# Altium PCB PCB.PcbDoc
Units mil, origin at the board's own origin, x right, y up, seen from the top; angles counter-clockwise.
Board outline 2700 x 2300 mil, 2 copper layers (Top Layer, Bottom Layer), stack 62 mil thick; 67 components, 35 nets, 208 pads, 314 vias.
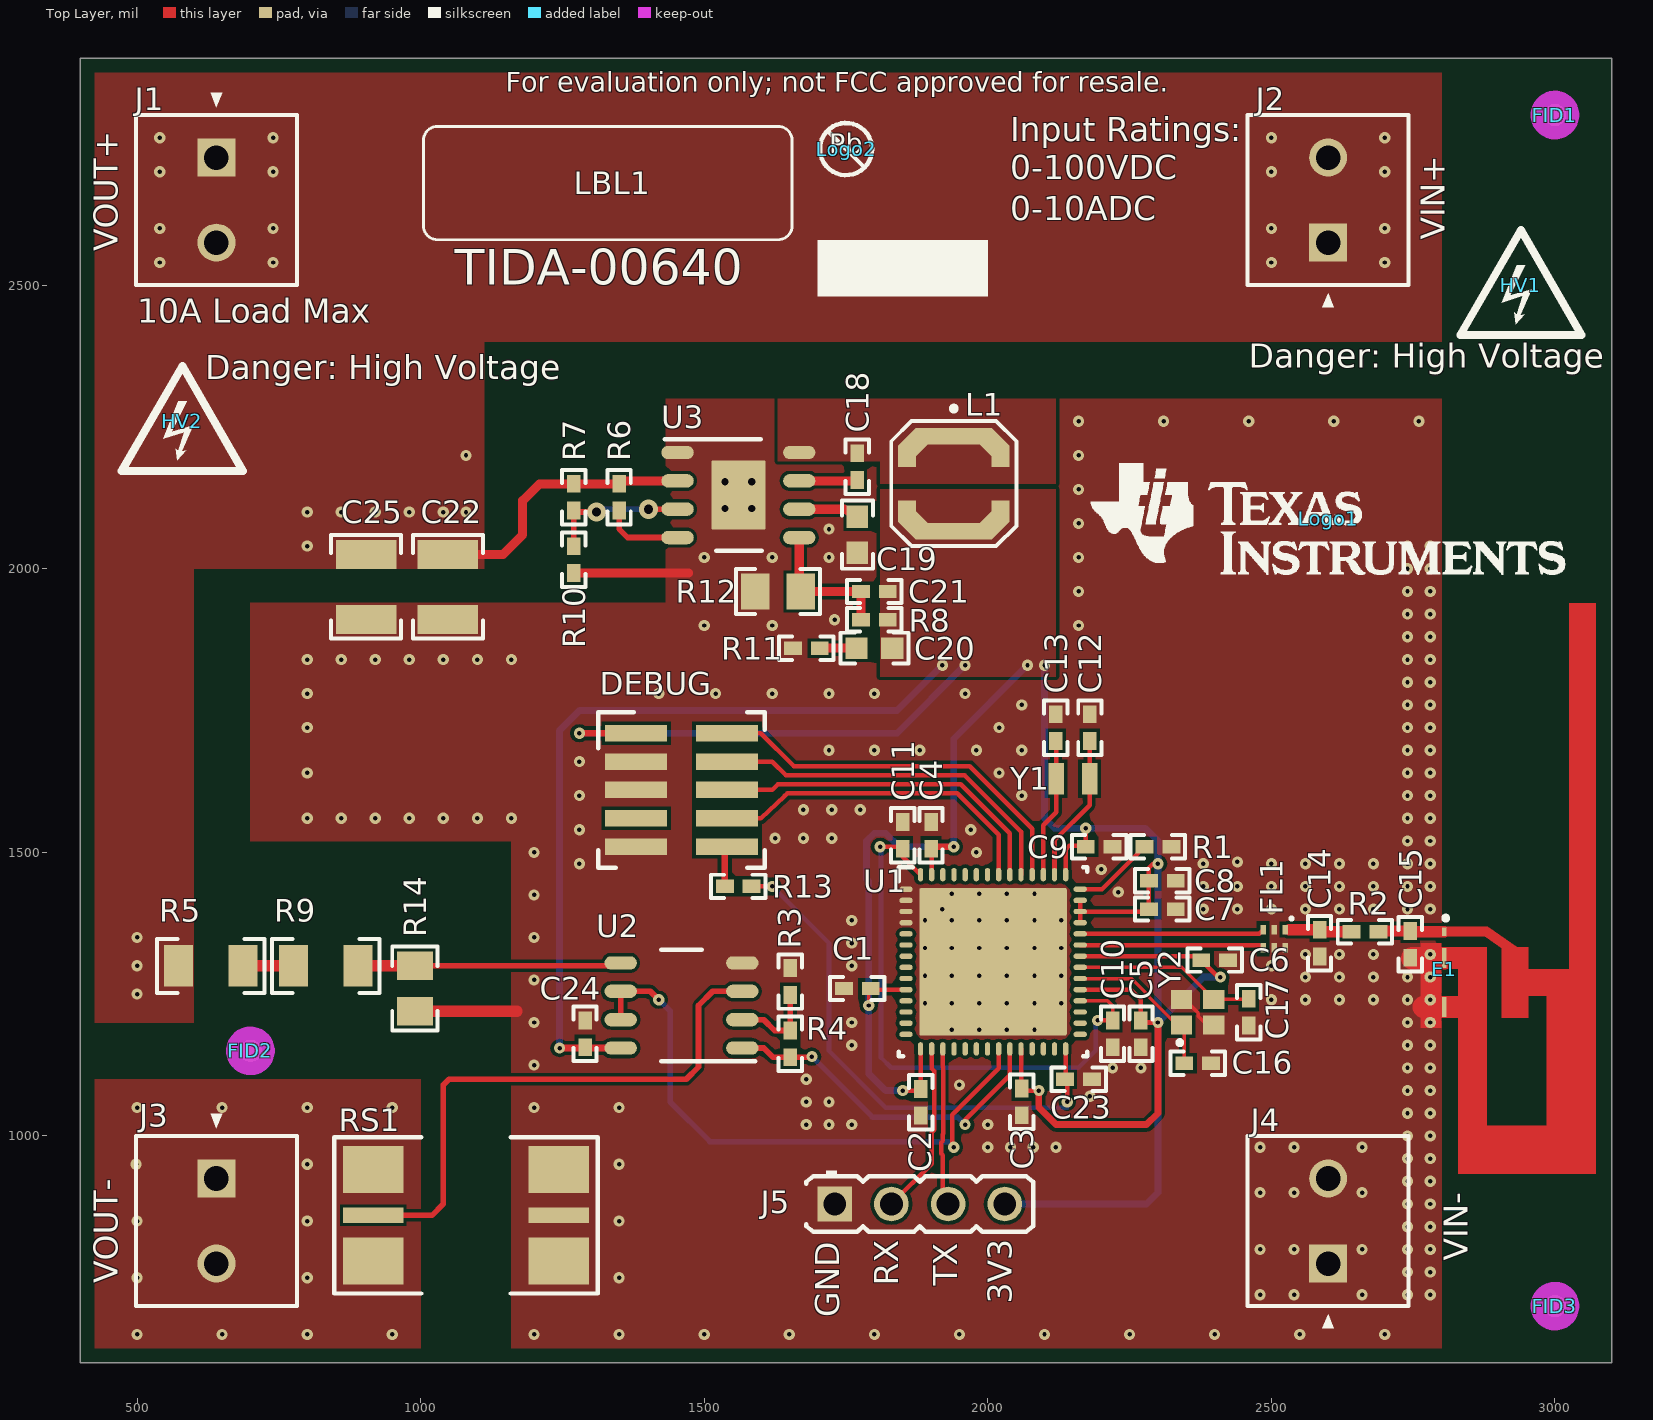
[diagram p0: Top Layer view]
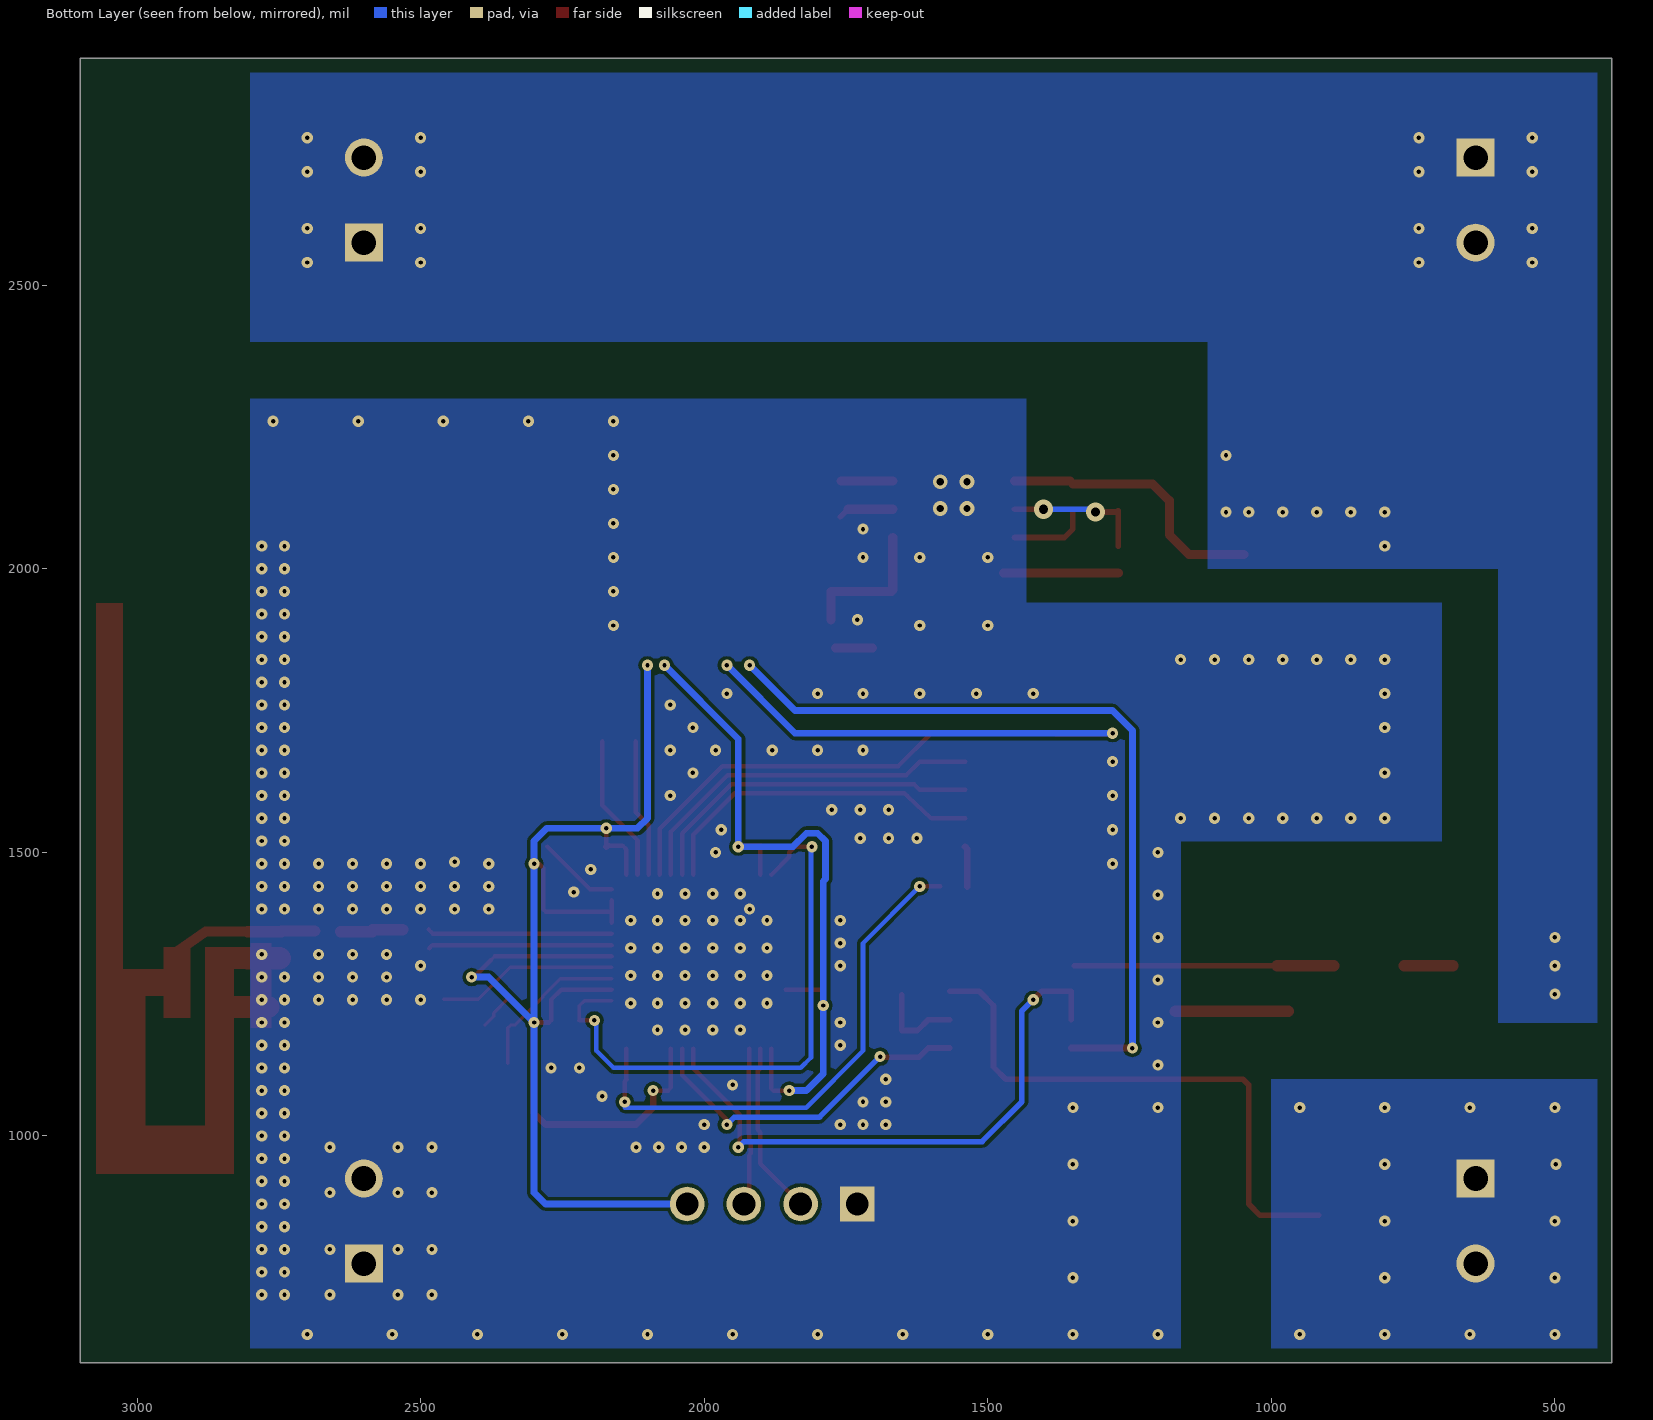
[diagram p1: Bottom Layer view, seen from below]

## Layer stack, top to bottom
Top Solder: solder mask 0.4, Solder Resist, Dk 3.5
Top Layer: signal copper 1.4
Dielectric1: core 59.2, FR-4, Dk 4.8
Bottom Layer: signal copper 1.4
Bottom Solder: solder mask 0.4, Solder Resist, Dk 3.5

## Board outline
400,2900 3100,2900 3100,600 400,600

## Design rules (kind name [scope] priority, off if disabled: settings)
AcuteAngle [All] p1: minimum=4.50000000000000E+0001 checktracksonly=FALSE
AssemblyTestPointUsage [All] p1: valid=2
BoardOutlineClearance BoardOutlineClearance_MountingHoles [OnCopper and InComponentClass('Mounting Holes')] p1: gap=40
BoardOutlineClearance BoardOutlineClearance_Poly [OnCopper and IsPoly] p2: gap=25
BoardOutlineClearance [OnCopper and Not InComponentClass('Logo') and not InComponentClass('FiducialMark') and not InRegion(1000,500,4000,800) and not InPoly] p3: gap=25
Clearance Clearance_Keepouts [((IsTrack Or IsArc) And Not InPoly) And IsFree and IsKeepOut vs ((IsTrack Or IsArc) And Not InPoly) And IsFree and IsKeepOut] p1: gap=0
Clearance Clearance_Poly [InPolygon] p2: gap=6
Clearance [All] p3: gap=7.87
ComponentClearance ComponentClearance_MountingHoles_FiducialMarks [InComponentClass('Mounting Holes') vs InComponentClass('FiducialMark')] p1: gap=50 collisioncheckmode=3 verticalgap=10 showdistances=FALSE
ComponentClearance ComponentClearance_Shunt [InComponentClass('Header') vs InComponentClass('Shunt')] p2: gap=0 collisioncheckmode=3 verticalgap=0 showdistances=FALSE
ComponentClearance ComponentClearance_Logo [InComponentClass('Logo')] p3: gap=50 collisioncheckmode=3 verticalgap=10 showdistances=FALSE
ComponentClearance ComponentClearance_ScrewToNut [(HasFootprint('NY PMS 440 0025 PH')) vs (HasFootprint('Keystone_1902C'))] p4: gap=5 collisioncheckmode=3 verticalgap=10 showdistances=FALSE
ComponentClearance ComponentClearance_MountingHoles [InComponentClass('Mounting Holes')] p5: gap=250 collisioncheckmode=3 verticalgap=100000 showdistances=FALSE
ComponentClearance ComponentClearance_SmallPassives [HasFootprint('0201*') or HasFootprint('0402*') or HasFootprint('0508') or HasFootprint('0603*') or HasFootprint('0612') or HasFootprint('0805*') or HasFootprint('0815*') or HasFootprint('0830*') or HasFootprint('1206*') or HasFootprint('1210*') or HasFootprint('1808*') or HasFootprint('1812*') or HasFootprint('1825*') or HasFootprint('2010*') or HasFootprint('2220*') or HasFootprint('2225*') or HasFootprint('2512*') or HasFootprint('2728*') or HasFootprint('3518*') vs HasFootprint('0201*') or HasFootprint('0402*') or HasFootprint('0508') or HasFootprint('0603*') or HasFootprint('0612') or HasFootprint('0805*') or HasFootprint('0815*') or HasFootprint('0830*') or HasFootprint('1206*') or HasFootprint('1210*') or HasFootprint('1808*') or HasFootprint('1812*') or HasFootprint('1825*') or HasFootprint('2010*') or HasFootprint('2220*') or HasFootprint('2225*') or HasFootprint('2512*') or HasFootprint('2728*') or HasFootprint('3518*')] p6: gap=14.96 collisioncheckmode=3 verticalgap=10 showdistances=FALSE
ComponentClearance ComponentClearance_THtoSMT [IsThruComponent vs IsSMTComponent] p7: gap=40 collisioncheckmode=3 verticalgap=30 showdistances=FALSE
ComponentClearance ComponentClearance_THtoTH [IsThruComponent vs IsThruComponent] p8: gap=30 collisioncheckmode=3 verticalgap=30 showdistances=FALSE
ComponentClearance [All] p9: gap=30 collisioncheckmode=3 verticalgap=10 showdistances=FALSE
DiffPairsRouting [All] p1: maxlimit=100 minlimit=10 mostfreqgap=10 toplayer_minwidth=15 toplayer_maxwidth=15 toplayer_prefwidth=15 bottomlayer_minwidth=15 bottomlayer_maxwidth=15 bottomlayer_prefwidth=15 maxuncoupledlength=1000
FabricationTestPointUsage TestPointUsage [All] p1: valid=2 allowmultiple=FALSE
FabricationTestpoint Testpoint [All] p1: side=3 testpointundercomponent=TRUE minsize=40 maxsize=100 preferedsize=60 minholesize=0 maxholesize=40 preferedholesize=32 testpointgrid=1 allowsidetop=TRUE allowsidebottom=TRUE usegrid=TRUE gridtolerance=0.01
FanoutControl Fanout_LCC [IsLCC] p1: bgadir=Out bgaviamode=Centered fanoutstyle=Auto fanoutdirection=Alternating viagrid=1 // Fanout_LCC (Default Rule)
FanoutControl Fanout_BGA [IsBGA] p2: bgadir=Out bgaviamode=Centered fanoutstyle=Auto fanoutdirection=Alternating viagrid=1 // Fanout_BGA (Default Rule)
FanoutControl Fanout_Default [All] p4: bgadir=Out bgaviamode=Centered fanoutstyle=Auto fanoutdirection=Alternating viagrid=1 // Fanout_Default (Default Rule)
FanoutControl Fanout_Small [(CompPinCount < 5)] p5: bgadir=Out bgaviamode=Centered fanoutstyle=Auto fanoutdirection=OutThenIn viagrid=1 // Fanout_Small (Default Rule)
HoleSize [All] p1: absolutevalues=TRUE maxlimit=251 minlimit=7.87 maxpercent=80.000 minpercent=20.000
MinimumAnnularRing MinimumAnnularRing_ThermalPadVias [IsVia and InAnyComponent] p1: minimumring=5.91
MinimumAnnularRing [All] p2: minimumring=8
MinimumSolderMaskSliver MinimumSolderMaskSliver_Logo [InComponentClass('Logo') vs InComponentClass('Logo')] p1: minsoldermaskwidth=0.7
MinimumSolderMaskSliver [All] p2: minsoldermaskwidth=3.94
PlaneConnect [All] p1: planeconnectstyle=Relief reliefexpansion=10 reliefentries=4 reliefconductorwidth=10 reliefairgap=10
PolygonConnect [All] p1: connectstyle=Direct reliefconductorwidth=10 reliefentries=4 polygonreliefangle="90 Angle" airgapwidth=10
RoutingVias ThermalPadVias [IsVia and InAnyComponent] p1: holewidth=7.87 width=19.68 viastyle="Through Hole" minholewidth=7.87 minwidth=19.68 maxholewidth=12.99 maxwidth=23.62
RoutingVias [All] p2: holewidth=16 width=34 viastyle="Through Hole" minholewidth=7.87 minwidth=26 maxholewidth=40 maxwidth=65
SilkToBoardRegionClearance [Not ((IsComment or IsDesignator) And (Hide <> 'False')) and not InRegion(1000,500,4000,800)] p1:
SilkToSilkClearance SilkToSilkClearance_Pb-FreeLogo [(HasFootprint('Pb-Free_Overlay_Medium') OR HasFootprint('Pb-Free_Overlay_Small')) vs (HasFootprint('Pb-Free_Overlay_Medium') OR HasFootprint('Pb-Free_Overlay_Small'))] p1: silktosilkclearance=0
SilkToSilkClearance [All] p2: silktosilkclearance=4
SilkToSolderMaskClearance SilkToComponentPadClearance [IsPad and InAnycomponent] p1: minsilkscreentomaskgap=5 clearancetoexposedcopper=TRUE
SilkToSolderMaskClearance "Silk to Solder Mask Opening" [All] p2: minsilkscreentomaskgap=4 clearancetoexposedcopper=FALSE
SolderMaskExpansion [All] p1: expansion=1.97
Width [All] p1: maxlimit=100 minlimit=6 preferedwidth=10 checkconnectedcopper=TRUE
15 further rules are at their usual default settings.

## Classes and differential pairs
component class PanelMonitor1: C1 C2 C3 C4 C5 C6 C7 C8 C9 C10 C11 C12 C13 C14 C15 C16 C17 C18 C19 C20 C21 C22 C23 C24 C25 DEBUG E1 FL1 J1 J2 J3 J4 J5 L1 R1 R2 R3 R4 R5 R6 R7 R8 R9 R10 R11 R12 R13 R14 RS1 U1 U2 U3 Y1 Y2
component class Logo: Logo1
component class EVM_Hardware: FID1 FID2 FID3 HV1 HV2 LBL1 Logo1 Logo2 Logo3 ZZ1 ZZ2 ZZ3 ZZ4
component class FiducialMark: FID1 FID2 FID3
component class AssemblyNote: ZZ1 ZZ2 ZZ3 ZZ4
component class Label: LBL1
component class Header: J5

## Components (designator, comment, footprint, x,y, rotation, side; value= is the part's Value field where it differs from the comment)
C1 "GRM155R70J104KA01D" 0402 1770,1260 r180 top
C2 "GRM155R70J104KA01D" 0402 1881.81,1059.37 r270 top
C3 "GRM155R70J104KA01D" 0402 2060,1060 r270 top
C4 "GRM155R61A105KE15D" 0402 1900,1530 r90 top
C5 "GRM155R70J104KA01D" 0402 2270,1180 r270 top
C6 "GRM155R70J104KA01D" 0402 2400,1310 r0 top
C7 "GRM1555C1H221JA01D" 0402 2307.72,1400 r0 top
C8 "GRM155R70J104KA01D" 0402 2307.72,1450 r0 top
C9 "GRM155R70J104KA01D" 0402 2196.25,1510 r0 top
C10 "GRM155R61A105KE15D" 0402 2220,1180 r270 top
C11 "GRM155R61A105KE15D" 0402 1850,1530 r90 top
C12 "GRM1555C1H220JA01D" 0402 2180,1720 r90 top
C13 "GRM1555C1H220JA01D" 0402 2120,1720 r90 top
C14 "0402YC132KAT2A" 0402 2585,1340 r270 top
C15 "0402YC132KAT2A" 0402 2745,1337.72 r270 top
C16 "GRM1555C1H120JA01D" 0402 2370,1128.19 r0 top
C17 "GRM1555C1H120JA01D" 0402 2460,1218.19 r270 top
C18 "GRM155R61C103KA01D" 0402 1770,2180 r90 top
C19 "GRM188R61C105KA93D" 0603 1770,2060 r270 top
C20 "GRM188R60J106ME47D" 0603 1800,1860 r180 top
C21 "GRM1555C1H751JA01D" 0402 1800,1960 r180 top
C22 "GRM32ER72A225KA35L" 1210_270 1048,1968 r90 top
C23 "GRM155R71H102KA01D" 0402 2160,1100 r0 top
C24 "C0402C104K4RACAUTO" 0402 1290,1180 r90 top
C25 "GRM32ER72A225KA35L" 1210_270 904,1968 r90 top
DEBUG "FTSH-105-01-L-DV-K" Samtec_FTSH-105-01-x-DV-K 1460,1610 r0 top
E1 "ANTENNA_DN007A" ANTENNA_DN007A 2805,1360 r270 top net-tie
FID1 "Fiducial" Fiducial10-20 3000,2800 r0 top
FID2 "Fiducial" Fiducial10-20 700,1150 r0 top
FID3 "Fiducial" Fiducial10-20 3000,700 r0 top
FL1 "LFB182G45BG5D920" Murata_LFB182G45BG5D920 2505,1347.72 r270 top
HV1 "DANGER HIGH VOLTAGE" IEC_HighVoltage_Small 2940,2500 r0 top
HV2 "DANGER HIGH VOLTAGE" IEC_HighVoltage_Small 580,2260 r0 top
J1 "1727010" PhoenixConact_1727010 640,2650 r270 top
J2 "1727010" PhoenixConact_1727010 2600,2650 r90 top
J3 "1727010" PhoenixConact_1727010 640,850 r270 top
J4 "1727010" PhoenixConact_1727010 2600,850 r90 top
J5 "0022284043" Molex_0022284043 1880,880 r0 top
L1 "LPS5030-334MLB" LPS5030 1940,2150 r270 top
LBL1 "Size: 0.65\" x 0.20 \"" Label_650x200 1330,2680 r0 top
Logo1 "Texas Instruments" TI_Stacked_Overlay_Small 2600,2088 r0 top
Logo2 "Pb-Free Symbol" Pb-Free_Overlay_Small 1750,2740 r0 top
Logo3 "FCC disclaimer" FCC_disclaimer 2350,3380 r0 top
R1 "RK73H1ETTP5602F" 0402 2300,1510 r0 top
R2 "CRCW04020000Z0ED" 0402 2665,1360 r0 top
R3 "CRCW04021K15FKED" 0402 1651.79,1272.28 r270 top
R4 "CRCW0402300KFKED" 0402 1651.79,1162.28 r270 top
R5 "CRCW1206249KFKEA" 1206 630,1300 r180 top
R6 "CRCW040288K7FKED" 0402 1350,2126.2 r90 top
R7 "CRCW040251K1FKED" 0402 1270,2126.2 r90 top
R8 "CRCW040210K0FKED" 0402 1800,1910 r0 top
R9 "CRCW1206249KFKEA" 1206 832.78,1300 r180 top
R10 "CRCW040213K0FKED" 0402 1270,2016.2 r90 top
R11 "CRCW04022R15FKED" 0402 1680,1860 r0 top
R12 "RT0805BRD076K12L" 0805_HV 1630,1960 r0 top
R13 "CRCW04022K20JNED" 0402 1560,1440 r180 top
R14 "ERJ-6ENF1002V" 0805_HV 990,1260 r90 top
RS1 "LRMAP3920B-R001FT" LRMAP3920B-R001FT 1080,860 r180 top
U1 "CC2538NF11RTQR" RTQ0056C 2009.37,1307.03 r0 top
U2 "TLV342AID" D0008A_N 1460,1230 r180 top
U3 "LM5017MRX/NOPB" DDA0008B_N 1560.32,2130 r0 top
Y1 "FC-12M 32.7680KA-A3" Epson_FC-12M 2150,1630 r180 top
Y2 "FA-128 32.0000MF20X-K3" Epson_FA-128 2370,1218.19 r90 top
ZZ1 "This Assembly Note is for PCB labels only" AssemblyNoteLabel 185,3938 r0 top
ZZ2 "These assemblies are ESD sensitive, ESD precautions shall be observed." AssemblyNote 185,3829.11 r0 top
ZZ3 "These assemblies must be clean and free from flux and all contaminants. Use of no clean flux is not acceptable." AssemblyNote 185,3740.56 r0 top
ZZ4 "These assemblies must comply with workmanship standards IPC-A-610 Class 2, unless otherwise specified." AssemblyNote 185,3652 r0 top

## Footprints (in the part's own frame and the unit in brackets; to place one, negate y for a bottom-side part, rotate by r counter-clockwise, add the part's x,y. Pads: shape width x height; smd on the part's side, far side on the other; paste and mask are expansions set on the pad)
0402 [mm] "0402 from SM-752 data"
  rect 0.8x0.6 smd: 1(-0.6,0) 2(0.6,0)
  silkscreen extent -1.22,-0.52 1.22,0.52, body extent -0.55,-0.3 0.55,0.3, height 0.6
0603 [mm] "0603 from SM-752 data"
  rect 1x0.95 smd: 1(-0.8,0) 2(0.8,0)
  silkscreen extent -1.52,-0.69 1.52,0.69, body extent -0.87,-0.47 0.87,0.47, height 1
0805_HV [mil] "0805 with 30mil clearance between pads"
  rect 50x63 smd: 1(-40,0) 2(40,0)
  silkscreen extent -74,-40 74,40, body extent -43,-29 43,29, height 57
1206 [mm] "1206 from SM-752 data"
  rect 1.3x1.85 smd: 1(-1.45,0) 2(1.45,0)
  silkscreen extent -2.4,-1.21 2.4,1.21, body extent -1.7,-0.9 1.7,0.9, height 1.35
1210_270 [mm] "1210"
  rect 1.3x2.7 smd: 1(-1.45,0) 2(1.45,0)
  silkscreen extent -2.32,-1.57 2.32,1.57, body extent -1.7,-1.35 1.7,1.35, height 2.7
ANTENNA_DN007A [mm] "SMD, 3-Leads"
  rect 0.4x0.2 smd paste-2 mask-2: 1(0,0)
  rect 0.9x0.2 smd paste-2 mask-2: 2(1.18,-0.01) 3(3.37,0)
  Top Layer region: 10.84,0.63 10.84,6.775 -14.715,6.775 -14.715,5.59 1.685,5.59 1.685,3.765 0.685,3.765 0.685,3.271 -0.225,1.951 -0.225,-0.11 0.21,-0.11 0.21,1.816 0.737,2.58 3.86,2.58 3.86,3.765 2.86,3.765 2.86,4.59 8.685,4.59 8.685,1.895 0.685,1.895 0.685,-0.11 1.66,-0.11 1.66,0.63 2.885,0.63 2.885,-0.11 3.86,-0.11 3.86,0.63
  silkscreen extent -0.71,-0.04 -0.51,0.16
AssemblyNote [mil] "Assembly Note"
AssemblyNoteLabel [mil] "Assembly Note for PCB Labels"
D0008A_N [mm] "SOIC, 8-Leads, Body 4.9x3.9mm, Pitch 1.27mm, IPC Medium Density"
  oval 1.45x0.6 smd: 1(-2.725,1.905) 2(-2.725,0.635) 3(-2.725,-0.635) 4(-2.725,-1.905) 5(2.725,-1.905) 6(2.725,-0.635) 7(2.725,0.635) 8(2.725,1.905)
  silkscreen extent -3.3,-2.5 0.9,2.5, body extent -3,-2.45 3,2.45, height 1.63
DDA0008B_N [mm] "SOIC, 8-Leads, Body 4.9x3.9mm, Pitch 1.27mm, Exposed Pad, IPC Medium Density"
  rrect100% 1.45x0.6 smd: 1(-2.725,1.905) 2(-2.725,0.635) 3(-2.725,-0.635) 4(-2.725,-1.905) 5(2.725,-1.905) 6(2.725,-0.635) 7(2.725,0.635) 8(2.725,1.905)
  rrect4% 2.41x3.1 smd: 9(0,0)
  silkscreen extent -3.3,-2.5 1.05,2.5, body extent -2.98,-2.45 2.98,2.45, height 1.55
Epson_FA-128 [mm] "Epson"
  rect 0.85x0.95 smd: 1(-0.575,0.725) 2(-0.575,-0.725) 3(0.575,-0.725) 4(0.575,0.725)
  silkscreen extent -1.43,0.73 -1.29,0.87, body extent -0.85,-1.05 0.85,1.05, height 0.51
Epson_FC-12M [mm] "Epson"
  rect 0.7x1.4 smd: 1(-0.75,0) 2(0.75,0)
  body extent -1.05,-0.63 1.05,0.63, height 0.6
FCC_disclaimer [mil]
Fiducial10-20 [mm]
  round 1 smd mask+0.5: 1(0,0)
  Top Layer keep-out circle w1.178: c0,0 r0.5
IEC_HighVoltage_Small [mil]
  silkscreen extent -107,-88 107,97
Label_650x200 [mil] "Thermal Transfer Label"
  silkscreen extent -325,-100 325,100, body extent -325,-100 325,100, height 1
LPS5030 [mm] "Coilcraft recommended land pattern.  Document 581-2, rev 10/06/08"
  rect 0.75x3.4 smd: 1(-2.125,0) 2(2.125,0)
  rect 1.131x0.92 smd rot 45: 1(-1.776,1.776) 2(1.776,-1.776)
  rect 1.131x0.92 smd rot 135: 1(-1.776,-1.776) 2(1.776,1.776)
  rect 0.95x0.8 smd: 1(-1.225,2.1) 1(-1.225,-2.1) 2(1.225,2.1) 2(1.225,-2.1)
  silkscreen extent -3.45,-2.8 2.8,2.8, body extent -2.5,-2.5 2.5,2.5, height 3.02
LRMAP3920B-R001FT [mm] "SMT, 4-Leads, Body 10x5.2mm, Pin Spacing 8.3mm"
  rect 2.7x2.1 smd: 1(-4.15,-2.05) 1(-4.15,2.05) 2(4.15,-2.05) 2(4.15,2.05)
  rect 2.7x0.69 smd: 3(-4.15,0) 4(4.15,0)
  silkscreen extent -5.9,-3.5 5.9,3.5, body extent -5,-2.6 5,2.6, height 0.93
Molex_0022284043 [mm] "Header, 2.54mm, 4x1, TH"
  rect 1.55x1.55 hole 1.02: 1(-3.81,0)
  round 1.55 hole 1.02: 2(-1.27,0) 3(1.27,0) 4(3.81,0)
  silkscreen extent -5.08,-1.24 5.08,1.5, body extent -5.08,-1.24 5.08,1.24, height 8.4
Murata_LFB182G45BG5D920 [mm] "SMT, 6-Leads, Body 1.6x0.8mm, Pitch 0.5mm"
  rect 0.425x0.25 smd mask+0.07: 1(-0.413,0.5) 2(-0.413,0) 3(-0.413,-0.5) 4(0.412,-0.5) 5(0.412,0) 6(0.412,0.5)
  silkscreen extent -0.91,0.77 -0.89,0.78, body extent -0.45,-0.85 0.45,0.85, height 0.65
Pb-Free_Overlay_Small [mil]
  silkscreen extent -46,-46 46,46
PhoenixConact_1727010 [mm]
  rect 1.7x1.7 hole 1.1: 1(-1.905,0)
  round 1.7 hole 1.1: 2(1.905,0)
  silkscreen extent -4.8,-3.6 3.81,3.6, body extent -3.81,-3.6 3.81,3.7, height 8.52
RTQ0056C [mm] "QFN, 56-Leads, Body 8x8mm, Pitch 0.5mm, Thermal Pad 6.6x6.6mm"
  rrect100% 0.6x0.24 smd: 1(-3.9,3.25) 2(-3.9,2.75) 3(-3.9,2.25) 4(-3.9,1.75) 5(-3.9,1.25) 6(-3.9,0.75) 7(-3.9,0.25) 8(-3.9,-0.25) 9(-3.9,-0.75) 10(-3.9,-1.25) 11(-3.9,-1.75) 12(-3.9,-2.25) 13(-3.9,-2.75) 14(-3.9,-3.25) 29(3.9,-3.25) 30(3.9,-2.75) 31(3.9,-2.25) 32(3.9,-1.75) 33(3.9,-1.25) 34(3.9,-0.75) 35(3.9,-0.25) 36(3.9,0.25) 37(3.9,0.75) 38(3.9,1.25) 39(3.9,1.75) 40(3.9,2.25) 41(3.9,2.75) 42(3.9,3.25)
  rrect100% 0.24x0.6 smd: 15(-3.25,-3.9) 16(-2.75,-3.9) 17(-2.25,-3.9) 18(-1.75,-3.9) 19(-1.25,-3.9) 20(-0.75,-3.9) 21(-0.25,-3.9) 22(0.25,-3.9) 23(0.75,-3.9) 24(1.25,-3.9) 25(1.75,-3.9) 26(2.25,-3.9) 27(2.75,-3.9) 28(3.25,-3.9) 43(3.25,3.9) 44(2.75,3.9) 45(2.25,3.9) 46(1.75,3.9) 47(1.25,3.9) 48(0.75,3.9) 49(0.25,3.9) 50(-0.25,3.9) 51(-0.75,3.9) 52(-1.25,3.9) 53(-1.75,3.9) 54(-2.25,3.9) 55(-2.75,3.9) 56(-3.25,3.9)
  rrect2% 6.6x6.6 smd paste-3.3: 57(0,0)
  silkscreen extent -4.23,-4.23 4.22,4.23, body extent -4.08,-4.07 4.07,4.08, height 1.01
Samtec_FTSH-105-01-x-DV-K [mm] "Header(Shrouded), 1.27mm, 5x2, SMT"
  rect 2.79x0.74 smd: 1(-2.035,2.54) 2(2.035,2.54) 3(-2.035,1.27) 4(2.035,1.27) 5(-2.035,0) 6(2.035,0) 7(-2.035,-1.27) 8(2.035,-1.27) 9(-2.035,-2.54) 10(2.035,-2.54)
  silkscreen extent -3.73,-3.48 3.73,3.48, body extent -2.92,-3.18 2.92,3.17, height 6.13
TI_Stacked_Overlay_Small [mil]
  silkscreen extent -418,-98 418,98

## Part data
C1 C2 C3 C5 C6 C8 C9: "CAP, CERM, 0.1 µF, 6.3 V, +/- 10%, X7R, 0402"
C4 C10 C11: "CAP, CERM, 1 µF, 10 V, +/- 10%, X5R, 0402"
C7: "CAP, CERM, 220 pF, 50 V, +/- 5%, C0G/NP0, 0402"
C12 C13: "CAP, CERM, 22 pF, 50 V, +/- 5%, C0G/NP0, 0402"
C14 C15: "CAP, CERM, 1300 pF, 16 V, +/- 10%, X7R, 0402"
C16 C17: "CAP, CERM, 12 pF, 50 V, +/- 5%, C0G/NP0, 0402"
C18: "CAP, CERM, 0.01 µF, 16 V, +/- 10%, X5R, 0402"
C19: "CAP, CERM, 1 µF, 16 V, +/- 10%, X5R, 0603"
C20: "CAP, CERM, 10 µF, 6.3 V, +/- 20%, X5R, 0603"
C21: "CAP, CERM, 750 pF, 50 V, +/- 5%, C0G/NP0, 0402"
C22 C25: "CAP, CERM, 2.2 µF, 100 V, +/- 10%, X7R, 1210"
C23: "CAP, CERM, 1000 pF, 50 V, +/- 10%, X7R, 0402"
C24: "CAP, CERM, 0.1 µF, 16 V, +/- 10%, X7R, AEC-Q200 Grade 1, 0402"
DEBUG: "Header(Shrouded), 1.27mm, 5x2, Gold, SMT"
E1: "2.4GHz PCB Antenna.  There is nothing to buy or mount."
FID1 FID2 FID3: "Fiducial mark.  There is nothing to buy or mount."
FL1: "Filter, BandPass, 2.45GHz, SMD"
HV1 HV2: library part IEC_HighVoltage, "IEC 61010-1 High Voltage Warning"
J1 J2 J3 J4: "Conn Term Block, 2POS, 3.81mm, TH"
J5: "Header, 2.54mm, 4x1, Tin, TH"
L1: "Inductor, Shielded Drum Core, Ferrite, 330 µH, 0.2 A, 1.8 ohm, SMD"
LBL1: library part THT-14-423-10, "Thermal Transfer Printable Labels, 0.650\" W x 0.200\" H - 10,000 per roll"
Logo1: library part TI_Logo, "Texas Instrument Corporate Signature"
Logo2: library part Pb-Free
Logo3: library part FCC_disclaimer, "FCC_disclaimer"
R1: "RES, 56.0 k, 1%, 0.063 W, AEC-Q200 Grade 0, 0402"
R2: "RES, 0, 5%, 0.063 W, 0402"
R3: "RES, 1.15 k, 1%, 0.063 W, 0402"
R4: "RES, 300 k, 1%, 0.063 W, AEC-Q200 Grade 0, 0402"
R5 R9: "RES, 249 k, 1%, 0.25 W, 1206"
R6: "RES, 88.7 k, 1%, 0.063 W, 0402"
R7: "RES, 51.1 k, 1%, 0.063 W, 0402"
R8: "RES, 10.0 k, 1%, 0.063 W, 0402"
R10: "RES, 13.0 k, 1%, 0.063 W, 0402"
R11: "RES, 2.15, 1%, 0.063 W, 0402"
R12: "RES, 6.12 k, 0.1%, 0.125 W, 0805"
R13: "RES, 2.2 k, 5%, 0.063 W, 0402"
R14: "RES, 10.0 k, 1%, 0.125 W, 0805"
RS1: "RES, 0.001, 1%, 4 W, AEC-Q200 Grade 0, 3920"
U1: "A Powerful System-On-Chip for 2.4-GHz IEEE 802.15.4, 6LoWPAN and ZigBee Applications, RTQ0056F"
U2: "Low-Voltage, Rail-To-Rail Output CMOS Operational Amplifier, 1.5 to 5.5 V, -40 to 125 degC, 8-pin SOIC (D0008A), Green (RoHS & no Sb/Br)"
U3: "100V, 600mA Constant On-Time Synchronous Buck Regulator, DDA0008B"
Y1: "Crystal, 32.768kHz, 12.5pF, SMD"
Y2: "Crystal, 32MHz, 10pF, SMD"
ZZ1: library part AssemblyNoteLabel
ZZ2 ZZ3 ZZ4: library part AssemblyNote

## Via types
v1: diameter 19.68, hole 7.87, Top Layer to Bottom Layer, 308 vias
v2: diameter 25.98, hole 12.99, Top Layer to Bottom Layer, tented top, 4 vias
v3: diameter 34, hole 16, Top Layer to Bottom Layer, 2 vias

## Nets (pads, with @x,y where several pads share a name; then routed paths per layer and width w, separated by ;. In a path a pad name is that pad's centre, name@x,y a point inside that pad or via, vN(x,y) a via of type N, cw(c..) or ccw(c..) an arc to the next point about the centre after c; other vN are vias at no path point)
GND: C1.2 C2.2 C3.2 C4.2 C5.2 C6.2 C7.2 C8.2 C9.2 C10.2 C11.2 C12.2 C13.2 C14.2 C15.2 C16.2 C17.2 C19.2 C22.1 C23.2 C24.2 C25.1 DEBUG.3 DEBUG.5 DEBUG.9 E1.2 E1.3 FL1.2 FL1.5 FL1.6 J4.1 J4.2 J5.1 R1.2 R3.1 R10.1 R11.1 R12.1 R14.1 RS1.1 RS1.3 U1.1 U1.2 U1.3 U1.4 U1.57 U2.4 U3.1 U3.9 Y2.2 Y2.4 | length 562.6
  Top Layer w6: Y2.4 2346.99,1240.83 2371.03,1216.79 2371.03,1211.25 Y2.2@2386.73,1195.55
  Top Layer w16: R10.1 1472.58,1992.58
  Top Layer w20: R14.1@970,1220 1170,1220
  Top Layer w39.37: C15.2@2748.54,1313.54 E1.2 ; 2768.32,1227.32 E1.3
  other v1: 1200,650 1350,650 1500,650 1650,650 1800,650 1950,650 2100,650 2250,650 2400,650 2550,650 2700,650 2480,720 2540,720 2660,720 2740,720 2780,720 1350,750 2740,760 2780,760 2480,800 2540,800 2660,800 2740,800 2780,800 2740,840 2780,840 1350,850 2740,880 2780,880 2480,900 2540,900 2660,900 2740,920 2780,920 1350,950 2740,960 2780,960 2000,980 2040,980 2080,980 2120,980 2480,980 2540,980 2660,980 2740,1000 2780,1000 1680,1020 1720,1020 1760,1020 2000,1020 2740,1040 2780,1040 1200,1050 1350,1050 1680,1060 1720,1060 2180,1070 2740,1080 2780,1080 1950,1090 1680,1100 2220,1120 2270,1120 2740,1120 2780,1120 1200,1125 1760,1160 2740,1160 2780,1160 1936.38,1186.96 1985.04,1186.96 2033.7,1186.96 2082.36,1186.96 1200,1200 1760,1200 2740,1200 2780,1200 1889.29,1234.04 1936.38,1234.04 1985.04,1234.04 2033.7,1234.04 2082.36,1234.04 2129.45,1234.04 2500,1240 2560,1240 2620,1240 2680,1240 2740,1240 2780,1240 1200,1275 2560,1280 2620,1280 2680,1280 2740,1280 2780,1280 1889.29,1282.7 1936.38,1282.7 1985.04,1282.7 2033.7,1282.7 2082.36,1282.7 2129.45,1282.7 1760,1300 2500,1300 2560,1320 2620,1320 2680,1320 2780,1320 1889.29,1331.37 1936.38,1331.37 1985.04,1331.37 2033.7,1331.37 2082.36,1331.37 2129.45,1331.37 1760,1340 1200,1350 1760,1380 1889.29,1380.03 1936.38,1380.03 1985.04,1380.03 2033.7,1380.03 2082.36,1380.03 2129.45,1380.03 1920,1400 2380,1400 2440,1400 2500,1400 2560,1400 2620,1400 2680,1400 2740,1400 2780,1400 1200,1425 1936.38,1427.11 1985.04,1427.11 2033.7,1427.11 2082.36,1427.11 2230,1430 2380,1440 2440,1440 2500,1440 2560,1440 2620,1440 2680,1440 2740,1440 2780,1440 2200,1470 1280,1480 2380,1480 2500,1480 2560,1480 2620,1480 2680,1480 2740,1480 2780,1480 2440,1483.12 1200,1500 1980,1500 2740,1520 2780,1520 1625,1525 1675,1525 1725,1525 1280,1540 1970,1540 800,1560 860,1560 920,1560 980,1560 1040,1560 1100,1560 1160,1560 2740,1560 2780,1560 1675,1575 1725,1575 1775,1575 1280,1600 2060,1600 2740,1600 2780,1600 800,1640 2020,1640 2740,1640 2780,1640 1280,1660 1720,1680 1800,1680 1880,1680 1980,1680 2060,1680 2740,1680 2780,1680 800,1720 2020,1720 2740,1720 2780,1720 2060,1760 2740,1760 2780,1760 800,1780 1420,1780 1520,1780 1620,1780 1720,1780 1800,1780 1960,1780 2740,1800 2780,1800 800,1840 860,1840 920,1840 980,1840 1040,1840 1100,1840 1160,1840 2740,1840 2780,1840 2740,1880 2780,1880 1500,1900 1620,1900 2160,1900 1730,1910 2740,1920 2780,1920 2160,1960 2740,1960 2780,1960 2740,2000 2780,2000 1500,2020 1620,2020 1720,2020 2160,2020 2740,2040 2780,2040 1720,2070 2160,2080 2160,2140 2160,2200 2160,2260 2310,2260 2460,2260 2610,2260 2760,2260
  other v2: 1536.69,2106.38 1583.94,2106.38 1536.69,2153.62 1583.94,2153.62
NetC10_1: C10.1 C11.1 U1.32 U1.56 | length 1030
  Top Layer w6: U1.32 2211.08,1238.14 2220,1229.21 C10.1
  Top Layer w8: v1(1810,1510) 1840,1510 1850,1500 1850,1491.99 U1.56 ; v1(2193.62,1203.62) C10.1
  Bottom Layer w8: v1(1810,1510) 1811.72,1508.28 1811.72,1138.28 1830,1120 2160,1120 2190,1150 v1@2190,1200
NetC14_1: C14.1 FL1.1 R2.1 | length 115.2
  Top Layer w19.68: 2531.26,1363.62 C14.1@2581.38,1363.62 ; C14.1 C14.1@2581.38,1363.62 ; R2.1 2585,1360 C14.1@2581.38,1363.62
NetC15_1: C15.1 E1.1 R2.2 | length 118.7
  Top Layer w19.68: R2.2@2686.34,1361.34 C15.1 ; C15.1@2745,1360 E1.1
NetC18_1: C18.1 U3.7 | length 91
  Top Layer w16: U3.7 C18.1@1758.62,2155
NetC18_2: C18.2 L1.1 U3.8
NetC19_1: C19.1 U3.6 | length 98
  Top Layer w10: 1746.5,2105 C19.1@1760,2091.5
  Top Layer w16: U3.6 1746.5,2105
NetC20_2: C20.2 R11.2 | length 64.9
  Top Layer w16: R11.2 C20.2
NetC21_2: C21.2 R8.1 R12.2 U3.5 | length 252.4
  Top Layer w10: R12.2@1667.6,1962.4 R12.2
  Top Layer w16: R12.2@1667.6,1962.4 U3.5 ; R12.2 C21.2 R8.1
NetC23_1: C23.1 R13.1 U1.28 | length 934.6
  Top Layer w8: R13.1 v1(1620,1440) ; U1.28 2137.32,1100.94 C23.1 2140,1096.38 v1(2140,1060)
  Bottom Layer w8: v1(1620,1440) 1720,1340 1720,1150 1820,1050 2140,1050 v1(2140,1060)
NetJ3_1: J3.1 J3.2 RS1.2
  other v1: 500,650 650,650 800,650 950,650 500,750 800,750 500,850 800,850 498.27,950 800,950 500,1050 650,1050 800,1050 950,1050
NetR1_1: R1.1 U1.42 | length 144.5
  Top Layer w8: U1.42 2201.37,1434.99 R1.1
NetR3_2: R3.2 R4.1 U2.2 | length 155.2
  Top Layer w10: U2.2 1605,1205 1624.09,1185.91 R4.1 R3.2
NetR5_1: R5.1 R9.2 | length 85.8
  Top Layer w20: R5.1@679.86,1300 R9.2@765.69,1300
NetR6_1: R6.1 U3.4 | length 141.8
  Top Layer w10: R6.1 1350,2070 1365,2055 U3.4
NetR7_1: R7.1 R10.2 U3.3 | length 258.9
  Top Layer w10: R10.2 R7.1 1272.58,2100 v3(1310,2100) ; v3(1401.8,2105) U3.3
  Bottom Layer w10: v3(1310,2100) 1320,2100 1315,2105 v3(1401.8,2105)
NetR9_1: R9.1 R14.2 U2.5 | length 477.9
  Top Layer w10: R14.2@970,1300 U2.5@1347.72,1300
  Top Layer w20: R9.1 R14.2
OSC32K1: C12.1 U1.44 Y1.1 | length 261
  Top Layer w8: U1.44 2117.64,1521.11 2179.53,1583 Y1.1 C12.1@2179.53,1695.91
OSC32K2: C13.1 U1.45 Y1.2 | length 244.7
  Top Layer w8: U1.45 2097.95,1547.95 2120.47,1570.47 Y1.2 C13.1@2120.47,1695.91
OSC32M1: C16.1 U1.34 Y2.1 | length 282.7
  Top Layer w6: U1.34 2253.53,1277.51 2284.87,1246.16 2284.87,1244.75 2334.07,1195.55 Y2.1 2346.38,1190.63 C16.1
OSC32M2: C17.1 U1.35 Y2.3 | length 319.4
  Top Layer w6: U1.35 2342.18,1297.19 Y2.3 C17.1@2459.02,1240.83
PVIN: C22.2 C25.2 J1.1 J1.2 J2.1 J2.2 R5.2 R6.2 R7.2 U3.2 | length 494
  Top Layer w10: R6.2 R6.2@1355.18,2155
  Top Layer w16: C22.2 1145.09,2025.09 1180,2060 1180,2120 1209.82,2149.82 R7.2 R6.2 ; R6.2@1355.18,2155 U3.2
  other v1: 500,1250 500,1300 500,1350 800,2040 800,2100 860,2100 920,2100 980,2100 1040,2100 1080,2100 1080,2200 540,2540 740,2540 2500,2540 2700,2540 540,2600 740,2600 2500,2600 2700,2600 540,2700 740,2700 2500,2700 2700,2700 540,2760 740,2760 2500,2760 2700,2760
RESET: DEBUG.10 R13.2 | length 71.5
  Top Layer w12: R13.2 1536.38,1506.26 DEBUG.10
RF_N: FL1.3 U1.38 | length 326.3
  Top Layer w8: U1.38 2478.25,1356.25 FL1.3@2486,1364
RF_P: FL1.4 U1.37 | length 324.4
  Top Layer w8: U1.37 2479.44,1336.56 FL1.4@2485,1331
RS+: RS1.4 U2.3 | length 1000.7
  Top Layer w10: RS1.4 1020,860 1040,880 1040,1090 1050,1100 1468.27,1100 1490,1121.73 1490,1230 1515,1255 U2.3
S_CUR: R4.2 U1.23 U2.1 | length 614
  Top Layer w8: v1(1960,1020) 1960,1028.25 2038.9,1107.15 U1.23
  Top Layer w10: U2.1 1605,1155 1621.34,1138.66 R4.2 v1@1688.66,1138.66
  Bottom Layer w10: v1(1690,1140) 1796.87,1033.13 1946.87,1033.13 v1(1960,1020)
S_VIN: U1.22 U2.6 U2.7 | length 1053.5
  Top Layer w8: v1@1937.28,982.72 1937.28,1037.28 2019.21,1119.21 U1.22
  Top Layer w10: U2.7 U2.6 1405,1255 v1(1420,1240) ; v1@1937.28,982.72 v1(1940,980)
  Bottom Layer w10: v1(1420,1240) 1440,1220 1440,1060 1510,990 1930,990 v1(1940,980)
TCK: DEBUG.4 U1.47 | length 645.4
  Top Layer w8: DEBUG.4 1620,1660 1644.13,1635.87 1959.02,1635.87 2058.58,1536.32 U1.47
TDI: DEBUG.8 U1.49 | length 597.2
  Top Layer w8: DEBUG.8 1600,1560 1641.42,1598.78 1646.77,1604.13 1945.87,1604.13 2019.21,1530.79 U1.49
TDO: DEBUG.6 U1.48 | length 611.7
  Top Layer w8: DEBUG.6 1620,1610 1630,1620 1952.45,1620 2038.9,1533.55 U1.48
TMS: DEBUG.2 U1.46 | length 689
  Top Layer w8: DEBUG.2 1600,1710 1658.25,1651.75 1968.25,1651.75 2078.27,1541.73 U1.46
UART_RXD: J5.2 U1.16 | length 306.6
  Top Layer w8: J5.2 1901.1,951.1 1901.1,1006.29 1905.5,1010.69 1905.5,1114.5 1901.1,1118.9 U1.16
UART_TXD: J5.3 U1.17 | length 279.9
  Top Layer w8: U1.17 1920.79,1121.66 1921.37,1121.08 1921.37,1003.53 1920.79,1002.95 1920.79,991.5 1918.28,989 1918.28,968.5 1920.79,966 1920.79,889.21 J5.3
VCC: C1.1 C2.1 C3.1 C4.1 C5.1 C6.1 C7.1 C8.1 C9.1 C20.1 C21.1 C24.1 DEBUG.1 J5.4 L1.2 R8.2 U1.10 U1.15 U1.24 U1.33 U1.36 U1.39 U1.40 U1.41 U1.43 U1.55 U2.8 | length 6391.8
  Top Layer w6: v1(1790,1230) 1790,1252.02 C1.1@1795.8,1257.82 ; C2.1@1878.03,1080 C2.1@1881.42,1083.39 ; C4.1 C4.1@1901.1,1505.28 ; C3.1@2058.58,1085.04 C3.1 C3.1@2063.62,1080 ; C5.1 C5.1@2273.62,1200 ; C6.1@2369.5,1316.88 C6.1 ; v1@2406.38,1280 v1(2410,1280)
  Top Layer w8: C1.1@1795.8,1257.82 U1.10 ; v1(1850,1080) C2.1@1878.03,1080 ; C2.1@1881.42,1083.39 U1.15 ; U1.55 C4.1@1901.1,1505.28 ; C3.1@2058.58,1085.04 U1.24 ; C3.1@2063.62,1080 v1(2090,1080) ; U1.43 2137.32,1505.32 2144,1512 C9.1@2170.63,1512 ; U1.33 2252.18,1257.82 2270,1240 C5.1 ; U1.36 C6.1@2369.5,1316.88 ; U1.39 U1.40 ; U1.41 U1.40 ; C9.1 v1(2172.63,1542.63) ; C5.1@2273.62,1200 v1(2300,1200) ; v1(2300,1480) 2291.65,1480 2284.09,1472.44 C8.1 C7.1 2279.71,1395.62 U1.40 ; C6.1 v1@2406.38,1280
  Top Layer w12: v1(1245,1155) U2.8 ; v1(1280,1710) DEBUG.1 ; C4.1@1900,1510 v1(1940,1510) ; v1(2090,1080) 2090,1050 2120,1020 2280,1020 2300,1040 v1(2300,1200) ; C9.1@2170.63,1512 C9.1
  Bottom Layer w12: v1(1245,1155) 1245,1715 1280,1750 1840,1750 v1(1920,1830) ; v1(1280,1710) 1840,1710 v1(1960,1830) ; v1(1850,1080) 1820,1080 1790,1110 v1(1790,1230) 1790,1449.22 1786.28,1452.93 1786.28,1519.82 1800.18,1533.72 1819.82,1533.72 1843.54,1510 v1(1940,1510) 1940,1700 v1(2070,1830) ; J5.4 2280,880 2300,900 v1(2300,1200) ; v1(2100,1830) 2100,1560 2117.37,1542.63 v1(2172.63,1542.63) 2277.37,1542.63 2300,1520 v1(2300,1480) v1(2300,1200) ; v1(2410,1280) 2380,1280 v1(2300,1200)
pads on no net: DEBUG.7 FID1.1 FID2.1 FID3.1 U1.5 U1.6 U1.7 U1.8 U1.9 U1.11 U1.12 U1.13 U1.14 U1.18 U1.19 U1.20 U1.21 U1.25 U1.26 U1.27 U1.29 U1.30 U1.31 U1.50 U1.51 U1.52 U1.53 U1.54

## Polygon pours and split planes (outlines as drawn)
GND on Top Layer "TOP_LAYER_GND_P010" (solid, remove dead copper, pour order 10): 1160,600 1160,1520 700,1520 700,1940 1432,1940 1432,2300 2800,2300 2800,600
NetC18_2 on Top Layer "TOP_LAYER_NETC18_2_P002" (solid, remove dead copper, pour order 2): 2120,2150.2 1810,2150.2 1810,2190 1630,2190 1630,2300 2120,2300
VCC on Top Layer "TOP_LAYER_VCC_P000" (solid, remove dead copper, pour order 0): 1810,2140 2120,2140 2120,1810 1810,1810
NetJ3_1 on Top Layer "TOP_LAYER_NETJ3_1_P008" (solid, remove dead copper, pour order 8): 400,1100 1000,1100 1000,600 400,600
PVIN on Top Layer "TOP_LAYER_PVIN_P004" (solid, remove dead copper, pour order 4): 400,2900 2800,2900 2800,2400 1112,2400 1112,2000 600,2000 600,1200 400,1200 400,2000
PVIN on Bottom Layer "BOTTOM_LAYER_PVIN_P016" (solid, remove dead copper, pour order 16): 400,2900 2800,2900 2800,2400 1112,2400 1112,2000 600,2000 600,1200 400,1200 400,2000
NetJ3_1 on Bottom Layer "BOTTOM_LAYER_NETJ3_1_P014" (solid, remove dead copper, pour order 14): 400,1100 1000,1100 1000,600 400,600
GND on Bottom Layer "BOTTOM_LAYER_GND_P018" (solid, remove dead copper, pour order 18): 1160,600 1160,1520 700,1520 700,1940 1432,1940 1432,2300 2800,2300 2800,600

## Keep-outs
Keep-Out Layer:
  text ".Layer_Name" at 577,-858.49 h60

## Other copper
Top Layer:
  rectangle net GND: 2762.81,1190 2800,1340
  text "String" at -500,2320 h72.83
  text ".Layer_Name" at 577,-858.49 h60
Bottom Layer:
  text ".Layer_Name" at 577,-858.49 h60

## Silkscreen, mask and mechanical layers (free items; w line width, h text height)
Top Overlay:
  region: 2000,2580 1700,2580 1700,2480 2000,2480
  text "Input Ratings:" at 2040,2740 h72.83
  text "0-100VDC / 0-10ADC" at 2040,2600 h72.83
  text "VIN+" at 2820,2580 h72.83 r90
  text "VOUT+" at 480,2560 h72.83 r90
  text "TIDA-00640" at 1060,2480 h108.27
  text "10A Load Max" at 500,2420 h72.83
  text "Danger: High Voltage" at 2460,2340 h72.83
  text "Danger: High Voltage" at 620,2320 h72.83
  text "VIN-" at 2860,780 h72.83 r90
  text "VOUT-" at 480,740 h72.83 r90
  text "RX" at 1856,736 h72.83 r90
  text "TX" at 1960,736 h72.83 r90
  text "3V3" at 2056,704 h72.83 r90
  text "GND" at 1752,680 h72.83 r90
  text ".Layer_Name" at 577,-858.49 h60
Bottom Overlay:
  text ".Layer_Name" at 577,-858.49 h60
Top Paste:
  text ".Layer_Name" at 577,-858.49 h60
Bottom Paste:
  text ".Layer_Name" at 577,-858.49 h60
Top Solder:
  text ".Layer_Name" at 577,-858.49 h60
  text ".Layer_Name" at 577,-858.49 h60
Bottom Solder:
  text ".Layer_Name" at 577,-858.49 h60
Drill Guide:
  text ".Layer_Name" at 577,-858.49 h60
M1 Board Outline:
  the board outline again, w10
  text ".Layer_Name" at 577,-858.49 h60
M2 Board Dimensions:
  rectangle: 0,-275 125,-150
  rectangle: 125,-400 500,-275
  lines w7: 0,-275 1000,-275 ; 125,-400 125,-150 ; 250,-400 250,-150 ; 500,-400 500,-150 ; 750,-400 750,-150 ; 0,-400 1000,-400 1000,-150 0,-150 0,-400
  text ".Layer_Name" at 577,-858.49 h60
M3 3D STEP Top:
  text ".Layer_Name" at 577,-858.49 h60
M4 3D STEP Bottom:
  text ".Layer_Name" at 577,-858.49 h60
M5 Assembly Top:
  lines w10: -292,-930.17 6308,-930.17 ; -292,-726.83 6310,-726.83 ; -292,-523.5 -292,-1133.5 3713,-1133.5 6310,-1133.5 6310,-523.5 -291.5,-523.5 -291.5,-1133.5 1284,-1133.5 ; 2173,-1133.5 2173,-523.5 ; 3440,-726.83 3440,-523.5 ; 4280,-726.83 4280,-523.5 ; 4902,-1140 4902,-937.17
  text "COMPONENTS MARKED 'DNP' SHOULD NOT BE POPULATED." at 1153.5,-318.5 h60
  text "ASSEMBLY VARIANT:" at 1153,-434 h60
  text ".VariantName" at 2189,-434 h60
  text "PCB VIEWED FROM TOP SIDE" at -228.5,-655.67 h60
  text "BOARD #:" at 2248,-655.67 h60
  text ".PRJ_Number" at 2793.5,-655.67 h60
  text "REV:" at 3638,-655.67 h60
  text ".PCB_Rev" at 3929.5,-655.67 h60
  text "SVN REV:" at 4476,-655.67 h60
  text ".VersionControl_RevNumber" at 4982,-655.67 h60
  text "TID #:" at 2248,-859 h60
  text ".TID" at 2793.5,-859 h60
  text "PLOT NAME =" at -228.5,-1064.34 h60
  text ".plot_File_Name" at 577,-1064.34 h60
  text "GENERATED    :" at 2250,-1064.34 h60
  text ".Print_Date" at 3119.5,-1064.34 h60
  text ".Print_Time" at 3848.5,-1064.34 h60
  text "TEXAS INSTRUMENTS" at 5113,-1064.34 h60
M6 Assembly Bottom:
  lines w10: -292.5,-727.33 6309.5,-727.33 ; -290.5,-930.67 6309.5,-930.67 ; 1115.5,-1140.5 1115.5,-937.67 ; 1737.5,-727.33 1737.5,-524 ; 2577.5,-727.33 2577.5,-524 ; 3844.5,-1134 3844.5,-524 ; 4733.5,-1134 6309,-1134 6309,-524 -292.5,-524 -292.5,-1134 2304.5,-1134 6309.5,-1134 6309.5,-524
  text "COMPONENTS MARKED 'DNP' SHOULD NOT BE POPULATED." at 6102,-318 h60
  text ".VariantName" at 5058,-434 h60
  text "ASSEMBLY VARIANT:" at 6097,-434 h60
  text ".VersionControl_RevNumber" at 1035.5,-656.17 h60
  text "SVN REV:" at 1541.5,-656.17 h60
  text ".PCB_Rev" at 2088,-656.17 h60
  text "REV:" at 2379.5,-656.17 h60
  text ".PRJ_Number" at 3224,-656.17 h60
  text "BOARD #:" at 3769.5,-656.17 h60
  text "PCB VIEWED FROM BOTTOM SIDE" at 6246,-656.17 h60
  text ".TID" at 3224,-859.5 h60
  text "TID #:" at 3769.5,-859.5 h60
  text "TEXAS INSTRUMENTS" at 904.5,-1064.84 h60
  text ".Print_Time" at 2169,-1064.84 h60
  text ".Print_Date" at 2898,-1064.84 h60
  text "GENERATED    :" at 3767.5,-1064.84 h60
  text ".plot_File_Name" at 5440.5,-1064.84 h60
  text "PLOT NAME =" at 6246,-1064.84 h60
M9 Title Sheet:
  drawing of 57 lines, arcs and shapes, not listed
  text "1" at 739.84,8036.5 h70
  text "2" at 3235.5,8036.5 h70
  text "3" at 5724.84,8036.5 h70
  text "4" at 8231.51,8036.5 h70
  text "5" at 10730.5,8036.5 h70
  text "6" at 13235.5,8036.5 h70
  text "A" at -416.5,6893.5 h70
  text "A" at 14383.5,6893.5 h70
  text "B" at -416.5,4513.5 h70
  text "B" at 14383.5,4513.5 h70
  text "C" at -416.5,2138.5 h70
  text "C" at 14383.5,2138.5 h70
  text "PROJECT TITLE:" at 11343.5,277.5 h45
  text ".PRJ_Title" at 11393.5,144.17 h70
  text "DESIGNED FOR:" at 11343.5,-23.5 h45
  text ".PRJ_Customer" at 11393.5,-163.5 h70
  text "D" at -416.5,-231.5 h70
  text "D" at 14383.5,-231.5 h70
  text "FILE NAME:" at 11343.5,-323.5 h45
  text ".PCB_File_Name_No_Path" at 11393.5,-443.5 h70
  text "Texas Instruments (TI) and/or its licensors do not warrant the accuracy or completeness of this specification" at 6374,-605.34 h45
  text "ENGINEER:" at 11343.5,-613.5 h45
  text "LAYOUT BY:" at 12848.5,-613.5 h45
  text "or any information contained therein. TI and/or its licensors do not warrant that this design will meet" at 6329.01,-718 h45
  text ".PRJ_Engineer" at 11393.5,-768.49 h70
  text ".PCB_Layout" at 12899,-768.49 h70
  text "the specifications, will be suitable for your application or fit for any particular purpose, or will operate in" at 6329.01,-830.67 h45
  text ".Layer_Name" at 577,-858.49 h60
  text "ALTIUM DESIGNER VERSION:" at 12848.5,-923.5 h45
  text "an implementation. TI and/or its licensors do not warrant that the design is production worthy. You should" at 6329.01,-943.33 h45
  text "completely validate and test your design implementation to confirm the system functionality for your application." at 6374,-1056 h45
  text ".print_Scale" at 11393.5,-1056.83 h70
  text ".Application_BuildNumber" at 12899,-1056.83 h70
  text "1" at 739.84,-1263.5 h70
  text "2" at 3235.5,-1263.5 h70
  text "3" at 5724.84,-1263.5 h70
  text "4" at 8231.51,-1263.5 h70
  text "5" at 10730.5,-1263.5 h70
  text "6" at 13235.5,-1263.5 h70
M10 Fab Notes:
  drawing of 173 lines, arcs and shapes, not listed
  text "DESIGN INFORMATION" at 12378.02,6201 h60
  text "MIN. TRACK WIDTH:" at 11733.46,6021 h60
  text "8" at 12829.7,6021 h60
  text "MIL" at 12984.46,6021 h60
  text "MIN. CLEARANCE:" at 11733.46,5889 h60
  text "0.2" at 12769.7,5889 h60
  text "mm" at 12984.46,5889 h60
  text "MIN. VIA PAD SIZE:" at 11733.46,5757 h60
  text "24" at 12799.71,5757 h60
  text "MIL" at 12984.46,5757 h60
  text "0.05mm (2MIL)" at 12428.46,5615.29 h60
  text "MINIMUM ANNULAR RING" at 11404.23,5611 h60
  text "EXTERNAL" at 13136.46,5611 h60
  text "PER" at 11604.23,5493 h60
  text "IPC-D-275 CLASS 2 LEVEL C" at 11824.23,5493 h60
  text "MIL, HOLES" at 13312.46,5380.71 h60
  text "+/-" at 12920,5380 h60
  text "+/-" at 13774,5380 h60
  text "REGISTRATION TOLERANCES:" at 11404.23,5375 h60
  text "METAL" at 12604,5375 h60
  text "5" at 13180.2,5375 h60
  text "3" at 14013.2,5375 h60
  text "MIL" at 14129.46,5375 h60
  text "+/-" at 13774,5262 h60
  text "HOLE SIZE TOLERANCE (UNLESS OTHERWISE SPECIFIED):" at 11404.23,5257 h60
  text "3" at 14013.2,5257 h60
  text "MIL" at 14129.46,5257 h60
  text "MATERIAL:" at 11329.46,5047.54 h60
  text "FR-4 High Tg" at 12315.9,4907.21 h60
  text "FR-408" at 11750.46,4898.64 h60
  text "OTHER" at 13238.46,4898.64 h60
  text "X" at 12161,4895 h60
  text "62 MIL (1.6mm) +/-10%" at 12070.56,4735.92 h60
  text "THICKNESS:" at 11404.23,4731.64 h60
  text "X" at 11942.4,4731.64 h60
  text "OTHER" at 13355.46,4731.64 h60
  text "TOLERANCE:" at 11404.23,4573.64 h60
  text "X" at 12243.53,4573.64 h60
  text "ANSI IPC-6012 TYPE 3 CLASS 2" at 12430.48,4573.64 h60
  text "OTHER +/-" at 12430.46,4417.64 h60
  text "BOW & TWIST:" at 11404.23,4260.64 h60
  text "X" at 12243.53,4260.64 h60
  text "ANSI IPC-6012 TYPE 3 CLASS 2" at 12430.48,4260.64 h60
  text "OTHER +/-" at 12430.46,4102.13 h60
  text "DRILLING:" at 11329.46,3963.64 h60
  text "REFERENCE:" at 11404.23,3846.64 h60
  text "X" at 12052.46,3846.64 h60
  text "AS SHOWN" at 12239.46,3846.64 h60
  text "X" at 12953.46,3846.64 h60
  text "NC_DRILL FILES" at 13090.46,3846.64 h60
  text "PTH COPPER THICKNESS:" at 11404.23,3688.64 h60
  text "X" at 12534.46,3688.64 h60
  text "20-30 um" at 12671.46,3688.64 h60
  text "OTHER" at 13388.46,3688.64 h60
  text "BOARD FINISH:" at 11329.46,3529.64 h60
  text "SILKSCREEN:" at 11484.68,3411.64 h60
  text "X" at 12433.46,3411.64 h60
  text "TOP" at 12559.46,3411.64 h60
  text "X" at 12943.46,3411.64 h60
  text "BOTTOM" at 13070.46,3411.64 h60
  text "SILKSCREEN COLOR:" at 11484.68,3244.64 h60
  text "X" at 12432.42,3244.64 h60
  text "WHITE" at 12559.46,3244.64 h60
  text "OTHER" at 13070.46,3244.64 h60
  text "X" at 12563.42,3085.44 h60
  text "GREEN" at 12690.46,3085.44 h60
  text "OTHER" at 13308.46,3085.44 h60
  text "SOLDER RESIST COLOR:" at 11484.68,3074.64 h60
  text "X" at 12563.42,2915.44 h60
  text "MATTE" at 12690.46,2915.44 h60
  text "SEMI-GLOSS" at 13308,2914.8 h60
  text "IMMERSION GOLD (ENIG)" at 12390.46,2726.92 h60
  text "ENEPIG" at 13728,2723.64 h60
  text "SURFACE FINISH:" at 11329.46,2722.64 h60
  text "X" at 12203.51,2722.64 h60
  text "IMM. TIN/SILVER OR EQUIV" at 11659,2565.64 h60
  text "OTHER" at 13090.46,2565.64 h60
  text "ARRAY/PANEL:" at 11329.46,2386.64 h60
  text "CUT AND TRIM PER M1 BOARD OUTLINE" at 12390.46,2382.35 h60
  text "N.C. ROUTE" at 12390.46,2230.64 h60
  text "X" at 13069.46,2230.64 h60
  text "V. SCORE" at 13256.46,2230.64 h60
  text "CERTIFICATION:" at 11329.46,2093.64 h60
  text "MATERIALS AND WORKMANSHIP FOR ALL PCBS" at 12054.46,2093.64 h60
  text "TO MEET OR EXCEED THE REQUIREMENTS OF:" at 12054.46,1995.64 h60
  text "X" at 11680.96,1859.13 h60
  text "ANSI IPC-A-600F CLASS ->" at 11819.96,1859.13 h60
  text "X" at 13459.02,1859.13 h60
  text "2" at 13577.96,1859.14 h60
  text "1" at 13262.96,1857.64 h60
  text "3" at 13931.96,1857.64 h60
  text "X" at 12495.02,1699.64 h60
  text "RoHS" at 12631.96,1699.64 h60
  text "OTHER" at 13276.36,1699.64 h60
  text "PER ORDER" at 13673.42,1699.64 h60
  text "ALL BOARDS MUST MEET OR EXCEED UL94-V0 REQUIREMENTS." at 11357,1534 h60
  text "PCB MUST BEAR THE UL94V-0 UL REGISTERED MATERIAL ID NUMBER" at 11357,1414 h60
  text "ADDITIONAL REQUIREMENTS:" at 11329.46,1240.64 h60
  text "MICROSECTION:" at 11404.23,1125.64 h60
  text "YES" at 12309.96,1125.64 h60
  text "REQUIRED" at 13171.46,969.49 h60
  text "BARE BOARD ELEC. TEST:" at 11404.23,966.64 h60
  text "NONE" at 12709.96,966.64 h60
  text "X" at 13044.46,966.64 h60
  text "PER ORDER" at 13763.46,966.64 h60
  text ".Layer_Name" at 577,-858.49 h60
M11 Gerber Information:
  lines w10: -292,-930.17 6308,-930.17 ; -292,-726.83 6310,-726.83 ; -292,-523.5 -292,-1133.5 3713,-1133.5 6310,-1133.5 6310,-523.5 -291.5,-523.5 -291.5,-1133.5 1284,-1133.5 ; 2173,-1133.5 2173,-523.5 ; 3440,-726.83 3440,-523.5 ; 4280,-726.83 4280,-523.5 ; 4902,-1140 4902,-937.17
  text "ALL ARTWORK VIEWED FROM TOP SIDE" at -228.5,-655.67 h60
  text "BOARD #:" at 2248,-655.67 h60
  text ".PRJ_Number" at 2793.5,-655.67 h60
  text "REV:" at 3638,-655.67 h60
  text ".PCB_Rev" at 3929.5,-655.67 h60
  text "SVN REV:" at 4476,-655.67 h60
  text ".VersionControl_RevNumber" at 4982,-655.67 h60
  text "LAYER NAME =" at -228.5,-858.49 h60
  text "TID #:" at 2248,-859 h60
  text ".TID" at 2793.5,-859 h60
  text "PLOT NAME =" at -228.5,-1064.34 h60
  text ".plot_File_Name" at 577,-1064.34 h60
  text "GENERATED    :" at 2250,-1064.34 h60
  text ".Print_Date" at 3119.5,-1064.34 h60
  text ".Print_Time" at 3848.5,-1064.34 h60
  text "TEXAS INSTRUMENTS" at 5113,-1064.34 h60
M12 Stackup:
  drawing of 191 lines, arcs and shapes, not listed
  text "Layer" at 9790.34,7830 h60
  text "Name" at 10200.26,7830 h60
  text "Material" at 11130,7830 h60
  text "Thickness" at 11989.77,7830 h60
  text "Constant" at 12639.6,7830 h60
  text "Board Layer Stack" at 13209.46,7830 h60
  text "1" at 9790.34,7710 h60
  text "Top Overlay" at 10200.26,7710 h60
  text "2" at 9790.34,7590 h60
  text "Top Solder" at 10200.26,7590 h60
  text "Solder Resist" at 11130,7590 h60
  text "0.40mil" at 11989.77,7590 h60
  text "3.5" at 12639.6,7590 h60
  text "3" at 9790.34,7470 h60
  text "Top Layer" at 10200.26,7470 h60
  text "Copper" at 11130,7470 h60
  text "1.40mil" at 11989.77,7470 h60
  text "4" at 9790.34,7350 h60
  text "Dielectric1" at 10200.26,7350 h60
  text "FR-4" at 11130,7350 h60
  text "59.20mil" at 11989.77,7350 h60
  text "4.8" at 12639.6,7350 h60
  text "5" at 9790.34,7230 h60
  text "Bottom Layer" at 10200.26,7230 h60
  text "Copper" at 11130,7230 h60
  text "1.40mil" at 11989.77,7230 h60
  text "6" at 9790.34,7110 h60
  text "Bottom Solder" at 10200.26,7110 h60
  text "Solder Resist" at 11130,7110 h60
  text "0.40mil" at 11989.77,7110 h60
  text "3.5" at 12639.6,7110 h60
  text "7" at 9790.34,6990 h60
  text "Bottom Overlay" at 10200.26,6990 h60
  text ".Layer_Name" at 577,-858.49 h60
M13 Component Bodies Top:
  text ".Layer_Name" at 577,-858.49 h60
M14 Component Bodies Bottom:
  text ".Layer_Name" at 577,-858.49 h60
M15 Courtyards Top:
  text ".Layer_Name" at 577,-858.49 h60
M16 Courtyards Bottom:
  text ".Layer_Name" at 577,-858.49 h60
Drill Drawing:
  lines w10: 5326.76,2926.43 5371.04,2926.43 5348.9,2882.15 5326.76,2926.43 ; 5326.76,2992.84 5337.83,2992.84 5337.83,2981.77 5359.97,2981.77 5359.97,2992.84 5371.04,2992.84 5371.04,3014.98 5359.97,3014.98 5359.97,3026.05 5337.83,3026.05 5337.83,3014.98 5326.76,3014.98 5326.76,2992.84 ; 5326.76,3081.4 5326.76,3092.47 5337.83,3103.54 5326.76,3114.6 5326.76,3125.67 5337.83,3125.67 5348.9,3114.6 5359.97,3125.67 5371.04,3125.67 5371.04,3114.6 5359.97,3103.54 5371.04,3092.47 5371.04,3081.4 5359.97,3081.4 5348.9,3092.47 5337.83,3081.4 5326.76,3081.4 ; 5326.76,3192.09 5337.83,3192.09 5348.9,3181.02 5359.97,3192.09 5371.04,3192.09 5359.97,3203.16 5371.04,3214.23 5359.97,3214.23 5348.9,3225.3 5337.83,3214.23 5326.76,3214.23 5337.83,3203.16 5326.76,3192.09 ; 5326.76,3280.64 5371.04,3280.64 5371.04,3324.92 5326.76,3324.92 5326.76,3280.64
  lines w12: 5286,2852.27 8398.94,2852.27 ; 5286,3350.38 8398.94,3350.38 ; 5601.63,2752.64 5601.63,3450 ; 5918.82,2752.64 5918.82,3450 ; 6540.56,2752.64 6540.56,3450 ; 6784.88,2752.64 6784.88,3450 ; 7145.22,2752.64 7145.22,3450 ; 7854.73,2752.64 7854.73,3450 ; 5286,2752.64 8398.94,2752.64 8398.94,3450 5286,3450 5286,2752.64
  text "Symbol" at 5345.77,3380.26 h72
  text "Quantity" at 5631.52,3380.26 h72
  text "Finished Hole Size" at 5948.7,3380.26 h72
  text "Plated" at 6570.45,3380.26 h72
  text "Hole Type" at 6814.77,3380.26 h72
  text "Drill Layer Pair" at 7175.11,3380.26 h72
  text "Hole Tolerance" at 7884.62,3380.26 h72
  text "308" at 5631.52,3280.64 h60
  text "7.87mil (0.200mm)" at 5948.7,3280.64 h60
  text "PTH" at 6570.45,3280.64 h60
  text "Round" at 6814.77,3280.64 h60
  text "Top Layer - Bottom Layer" at 7175.11,3280.64 h60
  text "4" at 5631.52,3181.02 h60
  text "12.99mil (0.330mm)" at 5948.7,3181.02 h60
  text "PTH" at 6570.45,3181.02 h60
  text "Round" at 6814.77,3181.02 h60
  text "Top Layer - Bottom Layer" at 7175.11,3181.02 h60
  text "2" at 5631.52,3081.4 h60
  text "16.00mil (0.406mm)" at 5948.7,3081.4 h60
  text "PTH" at 6570.45,3081.4 h60
  text "Round" at 6814.77,3081.4 h60
  text "Top Layer - Bottom Layer" at 7175.11,3081.4 h60
  text "4" at 5631.52,2981.77 h60
  text "40.16mil (1.020mm)" at 5948.7,2981.77 h60
  text "PTH" at 6570.45,2981.77 h60
  text "Round" at 6814.77,2981.77 h60
  text "Top Layer - Bottom Layer" at 7175.11,2981.77 h60
  text "8" at 5631.52,2882.15 h60
  text "43.31mil (1.100mm)" at 5948.7,2882.15 h60
  text "PTH" at 6570.45,2882.15 h60
  text "Round" at 6814.77,2882.15 h60
  text "Top Layer - Bottom Layer" at 7175.11,2882.15 h60
  text "326 Total" at 5631.52,2782.53 h60
  text ".Layer_Name" at 577,-858.49 h60
M17 Embedded Cavity:
  text ".Layer_Name" at 577,-858.49 h60
M18 Embedded Assembly:
  text ".Layer_Name" at 577,-858.49 h60
M19 Embedded Keepout:
  text ".Layer_Name" at 577,-858.49 h60

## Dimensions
0,-400 to 1000,-400 on M2 Board Dimensions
